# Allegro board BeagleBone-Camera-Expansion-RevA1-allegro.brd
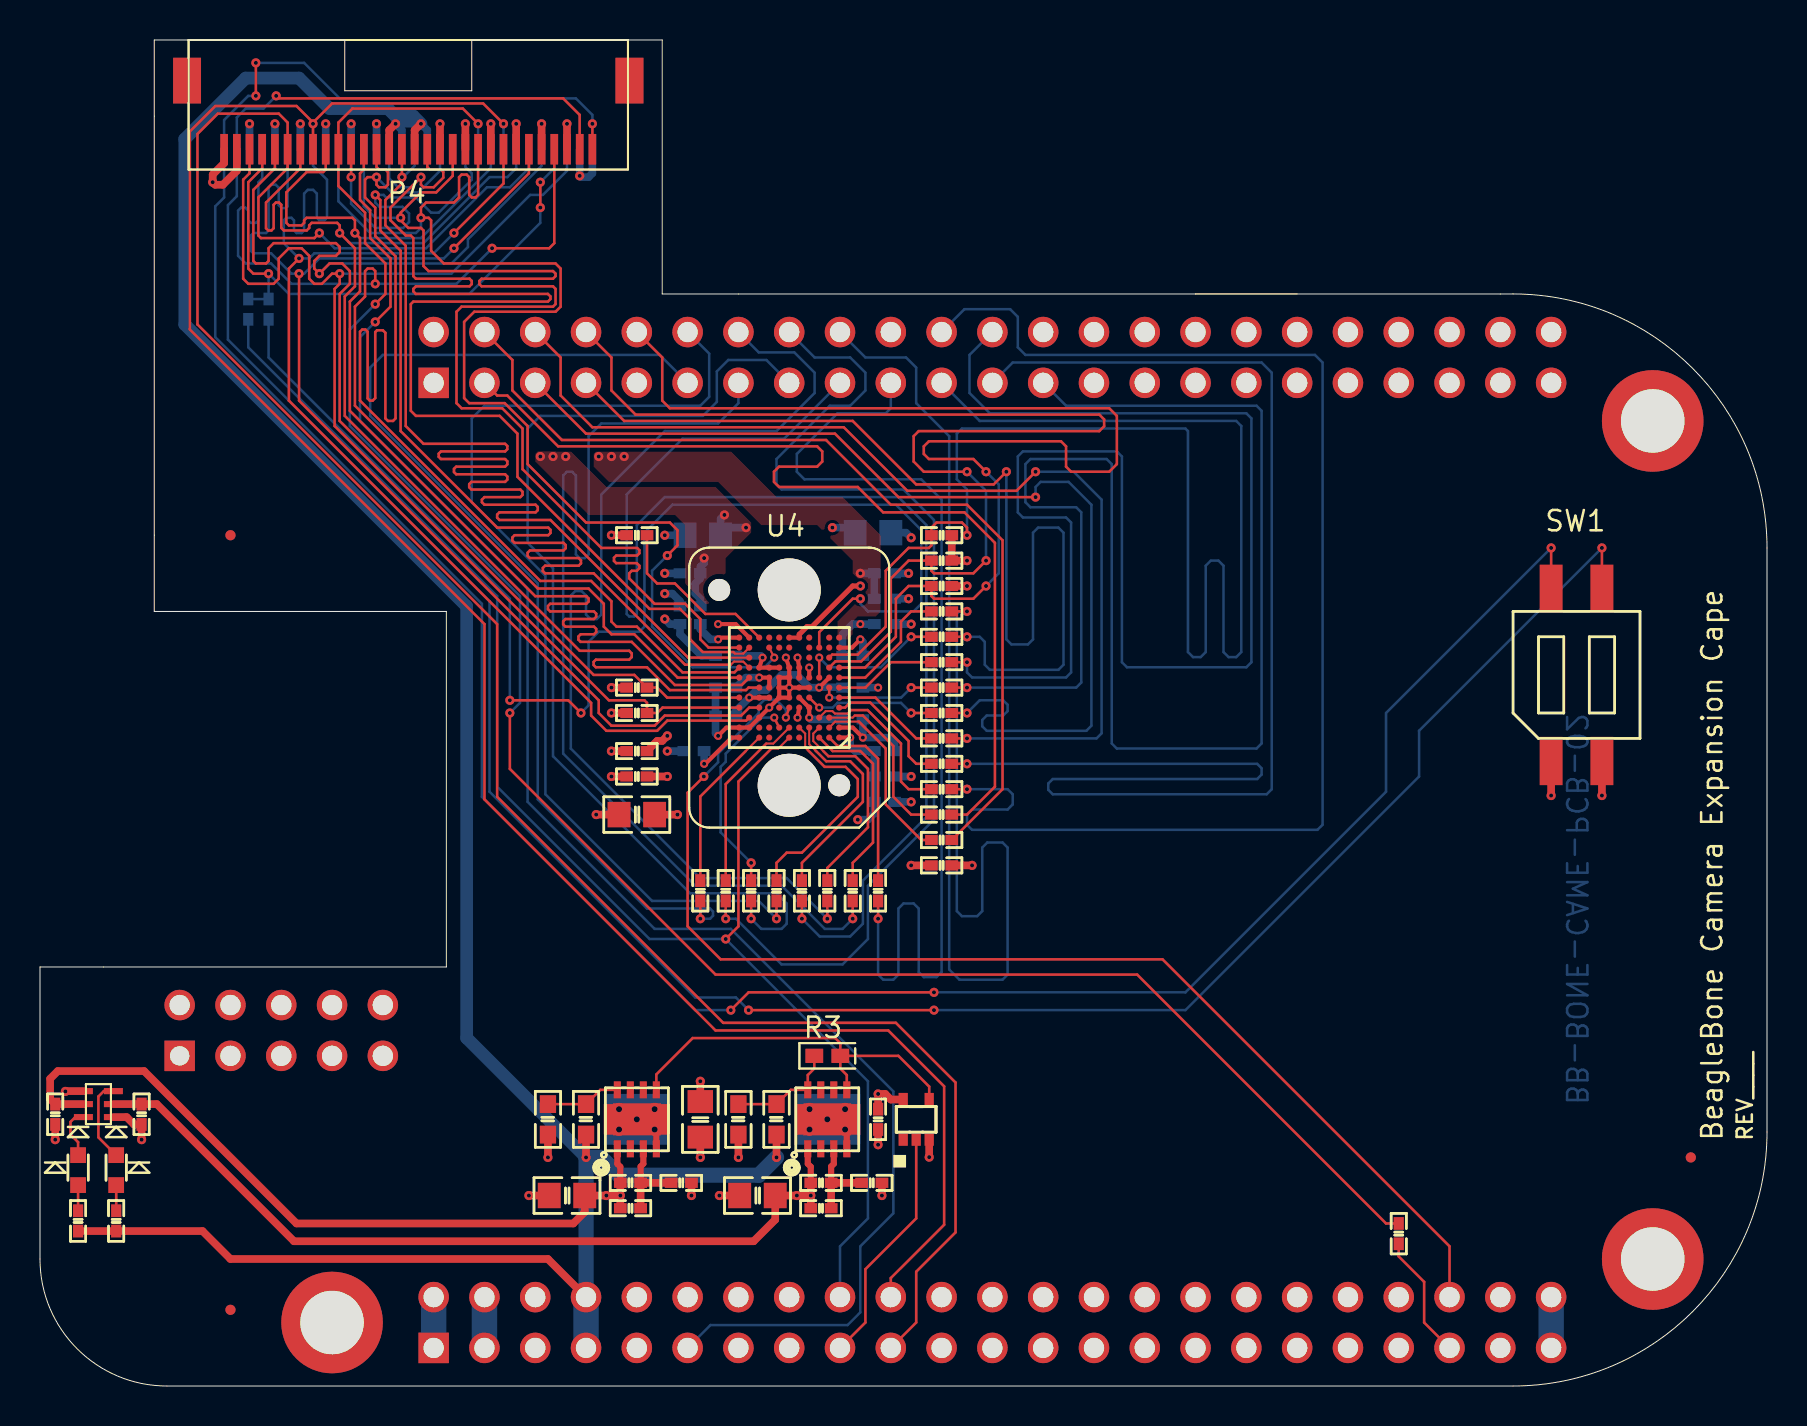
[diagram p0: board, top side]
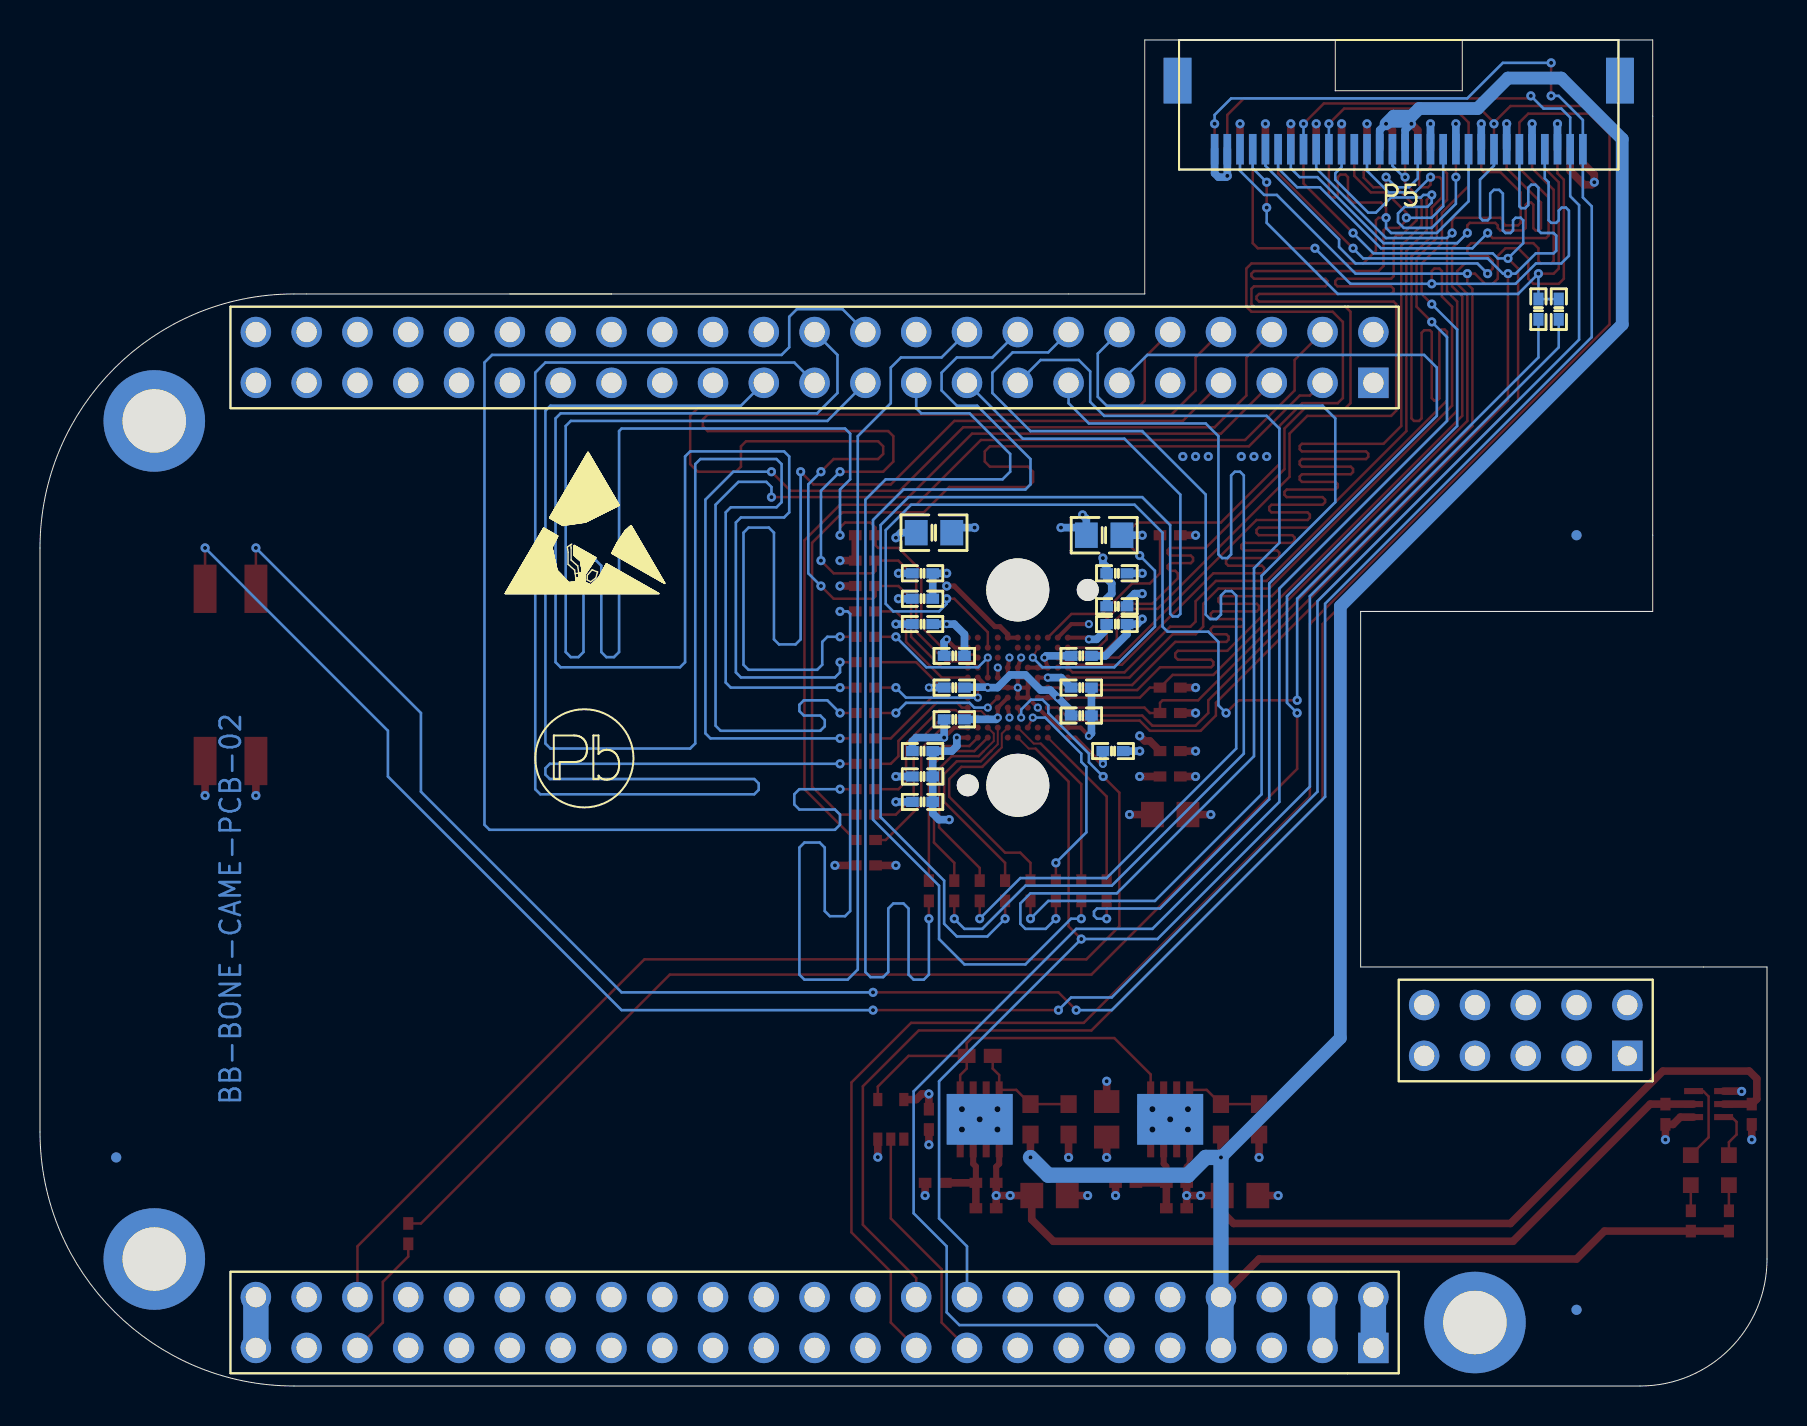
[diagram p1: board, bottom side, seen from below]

Outline 86.36 x 67.31 mm; copper layers: TOP, LYR2-GND, LYR3-PWR, BOTTOM. Coordinates in mm from the lower left corner of the outline.
Outline path: 57.78,54.61 31.11,54.61 31.11,67.31 21.59,67.31 21.59,64.77 15.24,64.77 15.24,67.31 5.71,67.31 5.71,38.73 20.32,38.73 20.32,20.95 0,20.95 0,6.35 arc(1.86,1.86) 6.35,0 73.66,0 arc(82.64,3.72) 86.36,12.7 86.36,41.91 arc(82.64,50.89) 73.66,54.61 57.78,54.61 ; 57.78,54.61 62.87,54.61

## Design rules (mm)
net group AD: nets AD0 AD1 AD2 AD3 AD4 AD5 AD6 AD7 AD8 AD9 AD10 AD11 AD12 AD13 AD14 AD15 GPMCCLK NADV
net group CAM: nets CAM_D0 CAM_D1 CAM_D2 CAM_D3 CAM_D4 CAM_D5 CAM_D6 CAM_D7 CAM_D8 CAM_D9 CAM_HSYNC CAM_PCLK CAM_VSYNC
net group GPMC: nets GPMC_AD0 GPMC_AD1 GPMC_AD2 GPMC_AD3 GPMC_AD4 GPMC_AD5 GPMC_AD6 GPMC_AD7 GPMC_AD8 GPMC_AD9 GPMC_AD10 GPMC_AD11 GPMC_AD12 GPMC_AD13 GPMC_AD14 GPMC_AD15 GPMC_CLK GPMC_NADV_ALE GPMC_NCS1 GPMC_NOE_NRE GPMC_NWE

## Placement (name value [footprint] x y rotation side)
C1  10uF,10V  [805]  33.02 13.34 270 top
C2  10uF,10V  [805]  29.84 28.57 0 top
C3  10uF,10V  [805]  35.88 9.53 0 top
C4  0.1uF  [402]  39.05 8.89 180 top
C5  0.1uF  [402]  29.53 8.89 180 top
C6  10uF,10V  [805]  26.35 9.53 0 top
C7  0.1uF  [402]  41.91 13.34 90 top
C8  0.1uF  [402]  40.64 33.34 180 bottom
C9  0.1uF  [402]  34.29 33.53 180 bottom
C10  0.1uF  [402]  32.7 31.75 180 bottom
C11  0.1uF  [402]  40.64 36.51 180 bottom
C12  0.1uF  [402]  34.29 36.51 180 bottom
C13  0.1uF  [402]  34.29 34.92 180 bottom
C14  0.1uF  [402]  45.09 26.04 180 top
C15  0.1uF  [402]  40.64 34.92 0 bottom
C16  0.1uF  [402]  32.51 38.1 180 bottom
C17  0.1uF  [402]  42.23 38.1 180 bottom
C18  0.1uF  [402]  29.84 31.75 180 top
C19  0.1uF  [402]  42.23 31.75 0 bottom
C20  0.1uF  [402]  32.51 38.99 180 bottom
C21  0.1uF  [402]  42.23 39.37 0 bottom
C22  0.1uF  [402]  32.51 40.64 180 bottom
C23  0.1uF  [402]  42.23 30.48 0 bottom
C24  0.1uF  [402]  42.23 40.64 0 bottom
C25  0.1uF  [402]  29.84 30.48 180 top
C26  0.1uF  [402]  42.23 29.21 0 bottom
C38  10uF,10V  [805]  41.66 42.67 0 bottom
C39  10uF,10V  [805]  33.15 42.55 0 bottom
D1  LTST-C190GKT  [LED2-31SQ]  3.81 10.79 270 top
D2  LTST-C190GKT  [LED2-31SQ]  1.91 10.79 270 top
NOREF  -  [unnamed]  80.64 48.26 0 top
NOREF#2  -  [#2]  86.36 12.7 0 top
NOREF#3  -  [unnamed]  82.55 11.43 0 top
NOREF#4  -  [#2]  0 0 0 top
NOREF#5  -  [#2]  0 0 0 top
NOREF#6  -  [#2]  1.84 1.88 0 top
NOREF#7  -  [#2]  80.64 6.35 0 top
NOREF#8  -  [unnamed]  80.64 6.35 0 top
NOREF#9  -  [#2]  14.61 3.17 0 top
NOREF#10  -  [#2]  81.6 2.79 0 top
NOREF#11  -  [unnamed]  9.53 3.81 0 top
NOREF#12  -  [unnamed#3]  37.47 34.92 180 top
NOREF#13  -  [#2]  80.64 6.35 0 top
NOREF#14  -  [unnamed]  14.61 3.17 0 top
NOREF#15  -  [#2]  -236.09 -292.66 0 top
NOREF#16  -  [#2]  14.61 3.17 0 top
NOREF#17  -  [unnamed]  9.53 42.55 0 top
NOREF#18  -  [#2]  0 20.95 0 top
NOREF#19  -  [#2]  20.32 20.95 0 top
NOREF#20  -  [#2]  80.64 48.26 0 top
NOREF#21  -  [#2]  5.71 38.73 0 top
NOREF#22  -  [#2]  -236.09 -292.66 0 top
NOREF#23  -  [unnamed]  82.55 11.43 180 bottom
NOREF#24  -  [unnamed]  9.53 42.55 180 bottom
NOREF#25  -  [unnamed]  9.53 3.81 180 bottom
P1  FEMALE HEADER 2x23  [HEADER23X2]  19.68 50.16 0 top
P2  FEMALE HEADER 2x23  [HEADER23X2]  19.68 1.91 0 top
P3  HDR5x2  [HEADER10X2]  6.99 16.51 90 top
P4  HEADER 15X2  [CON30SMD_245X865]  18.41 61.85 180 top
P5  HEADER 15X2  [CON30SMD_245X865]  18.41 61.85 0 bottom
Q1  DMC56404  [SMINI6-F3-B]  2.92 14.1 270 top
R1  0,DNI  [0603]  34.92 13.34 270 top
R2  0  [0603]  36.83 13.34 270 top
R3  10K  [0402]  39.37 16.51 180 top
R4  28K  [402]  39.05 10.16 180 top
R5  56.2K  [402]  41.59 10.16 0 top
R6  0,DNI  [0603]  25.4 13.34 270 top
R7  0  [0603]  27.3 13.34 270 top
R8  44.2k  [402]  29.53 10.16 180 top
R9  33.2k  [402]  32.07 10.16 0 top
R10  33  [402]  67.94 7.62 90 top
R11  10K,DNI  [402]  29.84 33.66 180 top
R12  33  [402]  45.09 31.11 180 top
R13  33  [402]  45.09 34.92 180 top
R16  33  [402]  45.09 36.2 180 top
R19  33  [402]  45.09 33.66 180 top
R22  10K,DNI  [402]  29.84 34.92 180 top
R23  33  [402]  45.09 32.38 180 top
R28  33  [402]  45.09 29.84 180 top
R29  33  [402]  45.09 28.57 180 top
R30  33  [402]  45.09 27.3 180 top
R31  33  [402]  41.91 24.77 90 top
R32  33  [402]  40.64 24.77 90 top
R33  33  [402]  39.37 24.77 90 top
R34  33  [402]  38.1 24.77 90 top
R35  33  [402]  36.83 24.77 90 top
R36  33  [402]  33.02 24.77 90 top
R37  33  [402]  34.29 24.77 90 top
R38  33  [402]  35.56 24.77 90 top
R39  33  [402]  45.09 38.73 180 top
R40  33  [402]  45.09 37.47 180 top
R41  10K,DNI  [402]  45.09 41.27 180 top
R42  10K,DNI  [402]  45.09 40.01 180 top
R43  10K,DNI  [402]  45.09 42.55 180 top
R44  0  [402]  10.41 53.85 270 bottom
R45  0, DNI  [402]  11.43 53.85 270 bottom
R55  470  [402]  3.81 8.26 270 top
R56  470  [402]  1.91 8.26 270 top
R59  10K  [402]  29.84 42.55 0 top
R121  100K,1%  [402]  5.08 13.59 270 top
R122  100K,1%  [402]  0.76 13.59 270 top
SW1  SW DIP-2  [SWDIP4_100-339SMD]  76.83 35.56 90 top
U1  TPS73701DRBR  [DRB8-14X33-PAD]  39.37 13.34 0 top
U2  TPS73701DRBR  [DRB8-14X33-PAD]  29.84 13.34 0 top
U3  SN74LVC1G07DCK  [DCK5]  43.81 13.34 0 top
U4  CSSP_6mmX6mm  [BGA86_6X6_P5MM]  37.47 34.92 180 top

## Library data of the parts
C1-C3 C6 C38 C39 = CAP_10uF_Y5V_10V_10%_0805
C4 C5 C7 = cap_0402_0r1uf_x7r_10v
C8-C26 = CAP,0.1uF
D1 D2 = LED_LTST-C150GKT: User Part Number: X; Tolerance: X
P1 P2 = HDR_46_F_2_0.1_0.1
P3 = HDR_10_F_2_0.1
P4 P5 = HEADER 15X2
Q1 = RN1907
R1-R3 R6 R7 R10 = ZeroOhmResistor1/16W0402
R4 R5 R8 R9 R11 R22 R41-R43 R59 = RES_0: tolerance: 1%
R12 R13 R16 R19 R23 R28-R40 R44 R45 = RES_33_0402
R55 R56 = RES_470_1/10W_5%_0402
R121 R122 = RES_100K_1/16W_1%_0402
SW1 = SW DIP-2
U1 U2 = TPS73701_0: Tolerance: X; User Part Number: X
U3 = SN74LVC1G06DCK_0: Tolerance: TOL; User Part Number: PART#
U4 = CSSP_0

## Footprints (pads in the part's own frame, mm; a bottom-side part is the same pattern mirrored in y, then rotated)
402
  rect 0.635x0.508 smd: 1(-0.508,0) 2(0.508,0)
0402
  rect 0.889x0.711 smd: 1(-0.65,0) 2(0.65,0)
0603
  rect 0.889x0.813 smd: 1(-0.762,0) 2(0.762,0)
805
  rect 1.143x1.27 smd: 1(-0.889,0) 2(0.889,0)
BGA86_6X6_P5MM
  round 0.305 smd: A1(-2.5,2.5) A2(-2,2.5) A3(-1.5,2.5) A5(-0.5,2.5) A6(0,2.5) A8(1,2.5) A9(1.5,2.5) A11(2.5,2.5) B1(-2.5,2) B2(-2,2) B3(-1.5,2) B4(-1,2) B5(-0.5,2) B6(0,2) B7(0.5,2) B8(1,2) B9(1.5,2) B10(2,2) B11(2.5,2) C2(-2,1.5) C3(-1.5,1.5) C9(1.5,1.5) C10(2,1.5) D1(-2.5,1) D4(-1,1) D5(-0.5,1) D6(0,1) D7(0.5,1) D9(1.5,1) D11(2.5,1) E1(-2.5,0.5) E4(-1,0.5) E5(-0.5,0.5) E6(0,0.5) E7(0.5,0.5) E8(1,0.5) E9(1.5,0.5) E11(2.5,0.5) F1(-2.5,0) F2(-2,0) F4(-1,0) F5(-0.5,0) F7(0.5,0) F8(1,0) F9(1.5,0) G1(-2.5,-0.5) G2(-2,-0.5) G3(-1.5,-0.5) G4(-1,-0.5) G5(-0.5,-0.5) G6(0,-0.5) G7(0.5,-0.5) G8(1,-0.5) G10(2,-0.5) G11(2.5,-0.5) H1(-2.5,-1) H2(-2,-1) H5(-0.5,-1) H6(0,-1) H7(0.5,-1) H8(1,-1) H9(1.5,-1) H10(2,-1) H11(2.5,-1) J2(-2,-1.5) J4(-1,-1.5) J10(2,-1.5) K1(-2.5,-2) K2(-2,-2) K3(-1.5,-2) K4(-1,-2) K6(0,-2) K7(0.5,-2) K8(1,-2) K10(2,-2) K11(2.5,-2) L1(-2.5,-2.5) L2(-2,-2.5) L4(-1,-2.5) L5(-0.5,-2.5) L6(0,-2.5) L7(0.5,-2.5) L8(1,-2.5) L9(1.5,-2.5) L10(2,-2.5) L11(2.5,-2.5)
CON30SMD_245X865
  rect 1.397x2.286 smd: (-11.062,-3.429) (11.062,-3.429)
  rect 0.381x1.524 smd: 1(8.572,0) 2(9.207,0) 3(7.303,0) 4(7.938,0) 5(6.032,0) 6(6.668,0) 7(4.763,0) 8(5.397,0) 9(3.493,0) 10(4.128,0) 11(2.223,0) 12(2.857,0) 13(0.953,0) 14(1.587,0) 15(-0.318,0) 16(0.318,0) 17(-1.587,0) 18(-0.953,0) 19(-2.857,0) 20(-2.223,0) 21(-4.128,0) 22(-3.493,0) 23(-5.397,0) 24(-4.763,0) 25(-6.668,0) 26(-6.032,0) 27(-7.938,0) 28(-7.303,0) 29(-9.207,0) 30(-8.572,0)
DCK5
  rect 0.46x0.66 smd: 1(-0.65,-0.991) 2(0,-0.991) 3(0.65,-0.991) 4(0.65,0.991) 5(-0.65,0.991)
DRB8-14X33-PAD
  rect 0.356x0.851 smd: 1(-0.975,-1.473) 2(-0.325,-1.473) 3(0.325,-1.473) 4(0.975,-1.473) 5(0.975,1.473) 6(0.325,1.473) 7(-0.325,1.473) 8(-0.975,1.473)
  rect 2.388x1.6 smd: 9(0,0)
HEADER10X2
  rect 1.524x1.524 hole 0.965: 1(0,0)
  round 1.524 hole 1.016: 2(2.54,0) 3(0,-2.54) 4(2.54,-2.54) 5(0,-5.08) 6(2.54,-5.08) 7(0,-7.62) 8(2.54,-7.62) 9(0,-10.16) 10(2.54,-10.16)
HEADER23X2
  rect 1.524x1.524 hole 1.016: 1(0,0)
  round 1.524 hole 1.016: 2(0,2.54) 3(2.54,0) 4(2.54,2.54) 5(5.08,0) 6(5.08,2.54) 7(7.62,0) 8(7.62,2.54) 9(10.16,0) 10(10.16,2.54) 11(12.7,0) 12(12.7,2.54) 13(15.24,0) 14(15.24,2.54) 15(17.78,0) 16(17.78,2.54) 17(20.32,0) 18(20.32,2.54) 19(22.86,0) 20(22.86,2.54) 21(25.4,0) 22(25.4,2.54) 23(27.94,0) 24(27.94,2.54) 25(30.48,0) 26(30.48,2.54) 27(33.02,0) 28(33.02,2.54) 29(35.56,0) 30(35.56,2.54) 31(38.1,0) 32(38.1,2.54) 33(40.64,0) 34(40.64,2.54) 35(43.18,0) 36(43.18,2.54) 37(45.72,0) 38(45.72,2.54) 39(48.26,0) 40(48.26,2.54) 41(50.8,0) 42(50.8,2.54) 43(53.34,0) 44(53.34,2.54) 45(55.88,0) 46(55.88,2.54)
LED2-31SQ
  rect 0.787x0.787 smd: 1(-0.749,0) 2(0.749,0)
SMINI6-F3-B
  rect 0.305x0.95 smd: 1(0.65,0.75) 2(0,0.75) 3(-0.65,0.75) 4(-0.65,-0.75) 5(0,-0.75) 6(0.65,-0.75)
SWDIP4_100-339SMD
  rect 2.413x1.143 smd: 1(-4.305,1.27) 2(-4.305,-1.27) 3(4.305,-1.27) 4(4.305,1.27)
unnamed
  round 5.08 hole 3.175: 1(0,0)
unnamed#3
  round 1.1 hole 1.1 unplated: (-2.5,4.885) (3.5,-4.885)
  round 3.15 hole 3.15 unplated: (0,4.885) (0,-4.885)

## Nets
1V8_FB: C4.1 R4.1(P1) R5.1(P1) U1.3(FB)
2V8_FB: C5.1 R8.1(P1) R9.1(P1) U2.3(FB)
DGND: C1.1 C2.1 C3.1 C6.1 C7.1 C8.1 C9.2 C10.2 C11.1 C12.2 C13.2 C14.1 C15.2 C16.2 C17.1 C18.2 C19.2 C20.2 C21.2 C22.2 C23.2 C24.2 C25.2 C26.2 C38.2 C39.1 P1.1 P1.2(26) P2.1 P2.2(26) P2.45(23) P2.46(48) P4.1 P4.2 P5.1 P5.2 Q1.1(4) Q1.4 R5.2(P2) R9.2(P2) R11.2(P2) R22.2(P2) R121.2 R122.2 SW1.1(A1) SW1.2(A2) U1.4(GND) U1.9(PAD) U2.4(GND) U2.9(PAD) U3.3(GND) U4.B1(GND1) U4.B10(CCMGND) U4.B11(GND2) U4.C9(CCMVCC1) U4.E6(GND11) U4.E7(GND12) U4.F4(GND3) U4.F5(GND4) U4.F7(GND5) U4.G6(GND6) U4.G7(GND7) U4.H6(GND8) U4.K1(GND9) U4.L5(GND13) U4.L6(GND14) U4.L10(GND10)
VDD_1V8: C2.2 C3.2 C4.2 C10.1 C13.1 C16.1 C19.1 C21.1 C23.1 C24.1 C25.1 C26.1 P4.25 P4.27 P5.25 P5.27 Q1.2(5) R4.2(P2) R121.1 U1.1(OUT) U4.A1(VCC1) U4.A11(VCC2) U4.D5(VCC3) U4.F8(VCC4) U4.G4(VCC5) U4.G8(VCC6) U4.L1(VCC7) U4.L11(VCC8)
VDD_2V8: C5.2 C6.2 C9.1 C12.1 C15.1 C18.1 C20.1 C22.1 C39.2 P4.21 P4.23 P5.21 P5.23 Q1.5 R8.2(P2) R122.1 U2.1(OUT) U4.E8(VCCIOA1) U4.E9(VCCIOA2) U4.G2(VCCIOB4) U4.H7(VCCIOB1) U4.H8(VCCIOB2) U4.H9(VCCIOB3)
VDD_3V3: C1.2 C7.2 C8.2 C11.2 C14.2 C17.2 C38.1 P2.3(2) P2.4(27) P4.17 P4.19 P5.17 P5.19 R1.2(P2) R6.2(P2) R41.1(P1) R42.1(P1) R43.1(P1) R59.1(P1) U3.5(VCC) U4.D4(VCCIOD1) U4.E5(VCCIOD2) U4.G5(VCCIOC1) U4.H5(VCCIOC2)
AD0: R13.2 U4.F2(GPMC_AD0)
AD1: R16.2 U4.F1(GPMC_AD1)
AD2: R19.2 U4.E4(GPMC_AD2)
AD3: R23.2 U4.E1(GPMC_AD3)
AD4: R12.2 U4.D1(GPMC_AD4)
AD5: R28.2 U4.C3(GPMC_AD5)
AD6: R29.2 U4.C2(GPMC_AD6)
AD7: R30.2 U4.B2(GPMC_AD7)
AD8: R31.2 U4.A2(GPMC_AD8)
AD9: R32.2 U4.A3(GPMC_AD9)
AD10: R33.2 U4.B3(GPMC_AD10)
AD11: R34.2 U4.B4(GPMC_AD11)
AD12: R35.2 U4.B5(GPMC_AD12)
AD13: R36.2 U4.A9(GPMC_AD13)
AD14: R37.2 U4.B6(GPMC_AD14)
AD15: R38.2 U4.B7(GPMC_AD15)
CAM_D0: P4.4 P5.4 R11.1(P1) U4.D11(CAM_D0)
CAM_D1: P4.6 P5.6 R22.1(P1) U4.E11(CAM_D1)
CAM_D2: P4.8 P5.8 U4.F9(CAM_D2)
CAM_D3: P4.10 P5.10 U4.G10(CAM_D3)
CAM_D4: P4.12 P5.12 U4.H10(CAM_D4)
CAM_D5: P4.14 P5.14 U4.H11(CAM_D5)
CAM_D6: P4.16 P5.16 U4.J10(CAM_D6)
CAM_D7: P4.18 P5.18 U4.K10(CAM_D7)
CAM_D8: P4.20 P5.20 U4.K11(CAM_D8)
CAM_D9: P4.22 P5.22 U4.K8(CAM_D9)
CAM_HSYNC: P4.26 P5.26 U4.D9(CAM_LINE_VALID)
CAM_MCLK: P4.9 P5.9 R10.2(P2)
CAM_PCLK: P4.28 P5.28 U4.G11(CAM_PCLK)
CAM_RESET: P4.3 P5.3 R44.1 R45.1
CAM_RST: R45.2 U4.K3(DNU8)
CAM_VSYNC: P4.24 P5.24 U4.C10(CAM_FRAME_VALID)
CLKOUT2: P2.41(21) R10.1(P1)
DMAR: P2.42(46) U4.D6(GPMC_DMAR)
GPIO0_4: P2.18(34) R44.2 U4.A6(NRESET)
GPIO0_5: P2.17(9) U3.2(A)
GPIO0_30: P2.11(6) P4.11
GPMC_AD0: P1.25(13) R13.1
GPMC_AD1: P1.24(37) R16.1
GPMC_AD2: P1.5(3) R19.1
GPMC_AD3: P1.6(28) R23.1
GPMC_AD4: P1.23(12) R12.1
GPMC_AD5: P1.22(36) R28.1
GPMC_AD6: P1.3(2) R29.1
GPMC_AD7: P1.4(27) R30.1
GPMC_AD8: P1.19(10) R31.1
GPMC_AD9: P1.13(7) R32.1
GPMC_AD10: P1.14(32) R33.1
GPMC_AD11: P1.17(9) R34.1
GPMC_AD12: P1.12(31) R35.1
GPMC_AD13: P1.11(6) R36.1
GPMC_AD14: P1.16(33) R37.1
GPMC_AD15: P1.15(8) R38.1
GPMC_CLK: P1.18(34) R39.1
GPMC_NADV_ALE: P1.7(4) R40.1
GPMC_NCS1: P1.21(11) R43.2(P2) U4.J2(GPMC_NCS)
GPMC_NOE_NRE: P1.8(29) R41.2(P2) U4.H2(GPMC_NOE)
GPMC_NWE: P1.10(30) R42.2(P2) U4.H1(GPMC_NWE)
GPMCCLK: R39.2 U4.G1(GPMC_CLK)
I2C2_SCL: P2.19(10) P4.5 P5.5
I2C2_SDA: P2.20(35) P4.7 P5.7
LDO_EN: R3.1(P1) U1.5(EN) U2.5(EN) U3.4(Y)
NADV: R40.2 U4.G3(GPMC_NADV)
SW1_A0: P4.29 P5.29 SW1.4(B1)
SW1_A1: P4.30 P5.30 SW1.3(B2)
SYS_5V: P2.7(4) P2.8(29) P4.13 P4.15 P5.13 P5.15 R2.2(P2) R7.2(P2) R55.2 R56.2
N17041351: R1.1(P1) R2.1(P1) R3.2(P2) U1.8(IN)
N17041584: R6.1(P1) R7.1(P1) U2.8(IN)
N17068057: R59.2(P2) U4.L9(VLP)
N17096906: D2.1(C) Q1.6(3)
N17096909: D2.2(A) R56.1
N17096919: D1.1(C) Q1.3
N17096922: D1.2(A) R55.1

Pads without a net: NOREF 1; NOREF#3 1; NOREF#8 1; NOREF#11 1; NOREF#14 1; NOREF#17 1; NOREF#23 1; NOREF#24 1; NOREF#25 1; P1 9 20 26 27 28 29 30 31 32 33 34 35 36 37 38 39 40 41 42 43 44 45 46; P2 5 6 9 10 12 13 14 15 16 21 22 23 24 25 26 27 28 29 30 31 32 33 34 35 36 37 38 39 40 43 44; P3 1 2 3 4 5 6 7 8 9 10; P5 11; U1 2 6 7; U2 2 6 7; U3 1; U4 A5 A8 B8 B9 D7 J4 K2 K4 K6 K7 L2 L4 L7 L8

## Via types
v1: diameter 0.457, hole 0.203, TOP to BOTTOM, 146 vias
v2: diameter 0.406, hole 0.203, TOP to BOTTOM, 26 vias
v3: diameter 0.635, hole 0.305, TOP to BOTTOM, 10 vias

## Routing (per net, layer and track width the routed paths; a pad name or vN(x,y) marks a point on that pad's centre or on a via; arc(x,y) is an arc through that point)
1V8_FB: length 4.6
  TOP w0.305: R4.1 39.56,10.98 39.7,11.11 U1.3
  TOP w0.381: R5.1 R4.1 C4.1
2V8_FB: length 4.6
  TOP w0.305: R8.1 30.04,10.98 30.17,11.11 U2.3
  TOP w0.381: R9.1 R8.1 C5.1
DGND: length 100.5
  TOP w0.203: U4.B1 40.65,32.93 v2(41.15,32.42) ; v2(37.47,34.92) U4.F5 U4.F4 ; v2(37.47,34.92) U4.F7 ; v2(37.47,34.92) U4.E6 U4.E7 ; v2(37.47,34.92) U4.G6 ; U4.F7 U4.E7 ; U4.F7 U4.G7 U4.G6 ; U4.G6 U4.H6 v2(37.3,36.43) ; U4.E7 v2(36.47,33.93) U4.C9 U4.B10 U4.B11 34.32,32.93 v2(33.91,32.51) ; v2(33.91,38.1) 34.79,38.1 U4.L10 ; v2(41.02,37.34) 40.61,36.92 U4.K1 ; U4.L6 U4.L5
  TOP w0.254: v1(41.02,40.01) 40.64,40.01 38.61,37.97 38.35,37.97 37.97,37.58 U4.L5
  TOP w0.305: U2.4 30.82,12.74 v3(30.73,12.83) ; v3(40.26,12.83) 40.35,12.74 U1.4
  TOP w0.381: v1(1.27,14.73) 1.28,14.75 Q1.4 ; C2.1 v1(27.81,28.57) ; R5.2 v1(42.1,9.53) ; C7.1 v1(41.91,12.06) ; R122.2 v1(0.76,12.32) ; C6.1 v1(24.45,9.53) ; C18.2 v1(28.57,31.75) ; C25.2 v1(28.57,30.48) ; R11.2 v1(28.57,33.66) ; C1.1 v1(33.02,15.24) ; P4.1 9.84,60.77 9.14,60.07 8.76,60.07 v1(8.64,60.2) 8.64,60.58 9.21,61.15 P4.2 ; R9.2 v1(32.58,9.53) ; C14.1 v1(46.61,26.04) ; SW1.2 v1(78.11,29.53) ; U3.3 v1(44.47,11.45) ; v1(28.57,34.92) R22.2 ; v1(5.08,12.32) R121.2 4.7,13.08 4.33,13.45 Q1.1 ; SW1.1 v1(75.56,29.53) ; C3.1 v1(33.97,9.53)
  LYR2-GND w1.016: P2.46 76.33,5.21 ; P2.46 74.8,3.68 ; P2.46 74.8,5.21 ; P2.46 76.33,3.68 ; 18.67,0.89 P2.1 ; P2.1 20.7,0.89 ; P2.1 20.7,2.92 ; P2.1 18.67,2.92 ; P2.2 20.45,3.68 ; P2.2 18.92,3.68 ; P2.2 18.92,5.21 ; P2.2 20.45,5.21 ; 18.67,49.15 P1.1 ; P1.1 20.7,51.18 ; P1.1 20.7,49.15 ; P1.1 18.67,51.18 ; 18.92,51.94 P1.2 ; P1.2 20.45,51.94 ; P1.2 20.45,53.47 ; P1.2 18.92,53.47 ; P2.45 76.33,1.14 ; P2.45 74.8,2.67 ; P2.45 74.8,1.14 ; P2.45 76.33,2.67
  BOTTOM w0.381: C17.1 v1(43.56,38.1) ; C10.2 v1(31.37,31.75) ; C39.1 v1(31.24,42.55) ; C11.1 41.15,37.21 v2(41.02,37.34) ; C26.2 v1(43.56,29.21) ; P5.2 27.62,60.64 27.43,60.45 27.05,60.45 v1(26.99,60.52) P5.1 ; C38.2 43.31,42.67 v1(43.56,42.42) ; C23.2 v1(43.56,30.48) ; C22.2 v1(31.24,40.64) ; C21.2 v1(43.43,39.37) ; C24.2 v1(43.43,40.64) ; v1(31.24,39.62) 31.62,39.62 32,39.24 C20.2 ; v1(31.24,38.35) 31.5,38.1 C16.2 32,37.59 33.08,36.51 C12.2 ; C15.2 v2(41.91,34.92) ; v2(33.91,32.51) 33.78,32.64 C9.2 C13.2 ; C8.1 v2(41.15,32.42) 42.55,32.42 42.74,32.23 C19.2
  BOTTOM w1.27: P2.1 P2.2 ; P2.45 P2.46
  vias: v3(28.96,13.84) v3(28.96,12.83) v3(29.84,13.34) v3(30.73,13.84) v3(38.48,13.84) v3(38.48,12.83) v3(39.37,13.34) v3(40.26,13.84)
VDD_1V8: length 66.8
  TOP w0.203: U4.L11 34,37.43 v2(33.91,37.34) ; v2(33.21,31.11) 33.21,31.05 34.58,32.42 U4.A11 ; U4.D5 v2(37.88,33.42) ; U4.F8 U4.G8 v2(35.96,35.43) ; U4.G4 v2(38.46,35.92) ; v2(40.51,32.42) U4.A1
  TOP w0.305: R4.2 38.54,10.96 38.39,11.11 U1.1
  TOP w0.381: v1(38.54,9.53) C4.2 ; v1(38.54,9.53) v1(37.85,9.53) C3.2 36.77,8.32 35.69,7.24 12.7,7.24 5.84,14.1 Q1.2 ; v1(38.54,9.53) R4.2 ; P4.27 v1(26.35,63.12) ; C2.2 v1(31.88,28.57) ; C25.1 v1(31.37,30.48) ; P4.25 v1(25.08,63.12)
  BOTTOM w0.381: v2(35.96,35.43) 35.3,35.43 C13.1 ; C16.1 33.02,37.85 33.53,37.34 v2(33.91,37.34) ; v2(40.51,32.42) 40.51,32 40.77,31.75 C19.1 C23.1 C26.1 41.72,28.64 41.4,28.32 v1(40.89,28.32) ; C21.1 C24.1 v1(41.02,40.64) ; C10.1 v2(33.21,31.11) ; P5.25 v1(11.75,63.12) ; P5.27 v1(10.48,63.12)
  vias: v1(27.94,46.48) v1(28.57,46.48) v1(29.21,46.48)
VDD_2V8: length 61.5
  TOP w0.203: U4.G2 v2(38.97,34.92) ; v2(35.47,34.42) U4.E9 U4.E8 ; U4.H7 U4.H8 U4.H9 v2(36.13,36.43)
  TOP w0.305: R8.2 29.02,10.96 28.87,11.11 U2.1
  TOP w0.381: v1(31.37,32.51) 31.11,32.26 30.86,32.26 C18.1 ; v1(29.02,9.53) v1(28.32,9.53) C6.2 27.24,8.7 26.67,8.13 12.83,8.13 5.21,15.75 0.89,15.75 0.51,15.37 0.51,14.35 0.76,14.1 Q1.5 ; v1(29.02,9.53) R8.2 ; v1(29.02,9.53) C5.2 ; P4.23 v1(23.81,63.12) ; P4.21 v1(22.54,63.12)
  BOTTOM w0.381: v1(33.21,41.4) 33.21,41.15 33.02,40.96 C22.1 33.02,40.39 32.77,40.13 32.77,39.62 33.02,39.37 C20.1 ; P5.23 v1(13.02,63.12) ; v1(34.23,43.56) 34.04,43.37 C39.2 34.42,42.93 v1(35.31,42.93) ; C12.1 36.04,36.51 v2(36.13,36.43) ; C9.1 34.8,33.76 v2(35.47,34.42) 35.84,34.8 36.32,34.8 37.08,35.56 37.85,35.56 38.48,34.92 v2(38.97,34.92) 38.99,34.95 40.11,34.95 C15.1 ; P5.21 v1(14.29,63.12)
  vias: v1(25.02,46.48) v1(25.65,46.48) v1(26.29,46.48)
VDD_3V3: length 34.4
  TOP w0.203: v2(37.88,36.43) U4.H5 U4.G5 ; v2(38.46,33.42) U4.D4 U4.E5
  TOP w0.381: U3.5 42.55,14.33 42.27,14.61 v1(41.91,14.61) C7.2 ; R1.2 v1(34.92,11.43) ; R42.1 v1(46.35,40.01) ; v1(46.35,41.27) R41.1 R43.1 ; P4.19 v1(21.27,63.12) ; C1.2 v1(33.02,11.43) ; C14.2 v1(43.56,26.04) ; R6.2 v1(25.4,11.43) ; v1(28.57,42.55) R59.1 ; P4.17 v1(20,63.12)
  LYR3-PWR w0.381: 38.46,33.42 v2(38.46,33.42)
  LYR3-PWR w1.016: P2.3 22.99,1.14 ; P2.3 22.99,2.67 ; P2.3 21.46,1.14 ; P2.3 21.46,2.67 ; P2.4 22.99,5.21 ; P2.4 21.46,3.68 ; P2.4 21.46,5.21 ; P2.4 22.99,3.68
  BOTTOM w0.381: v1(39.62,42.93) 40.51,42.93 40.77,42.67 ; P5.17 v1(16.83,63.12) ; C8.2 38.55,33.34 v2(38.46,33.42) ; C11.2 40.13,37.59 40.64,38.1 v2(41.02,38.1) C17.2 ; P5.19 v1(15.56,63.12)
  BOTTOM w1.27: P2.3 P2.4
AD0: length 5.8
  TOP w0.127: U4.F2 v2(39.46,34.42) ; R13.2 v1(43.56,34.92)
  BOTTOM w0.127: v2(39.46,34.42) 43.06,34.42 v1(43.56,34.92)
AD1: length 5.1
  TOP w0.127: R16.2 42.55,36.2 41.27,34.92 U4.F1
AD2: length 6.6
  TOP w0.127: R19.2 v1(43.56,33.66) ; U4.E4 v2(38.97,33.93)
  BOTTOM w0.127: v1(43.56,33.66) 43.05,34.16 39.88,34.16 39.64,33.93 v2(38.97,33.93)
AD3: length 5.5
  TOP w0.127: U4.E1 41.78,34.42 43.81,32.38 R23.2
AD4: length 6.4
  TOP w0.127: U4.D1 40.26,33.93 40.51,34.17 41.52,34.17 43.43,32.26 43.43,31.5 43.81,31.11 R12.2
AD5: length 8.6
  TOP w0.102: U4.C3 39.29,33.75 39.63,33.75 39.75,33.63 40.39,33.63 40.56,33.8
  TOP w0.127: R28.2 43.43,29.84 43.05,30.23 43.05,32.13 41.38,33.8 40.56,33.8
AD6: length 8.7
  TOP w0.102: U4.C2 40.64,33.42 40.74,33.53
  TOP w0.127: 40.74,33.53 41.15,33.53 42.67,32 42.67,29.46 43.56,28.57 R29.2
AD7: length 9.3
  TOP w0.102: 40.94,33.22 39.76,33.22 U4.B2
  TOP w0.127: R30.2 44.07,27.3 42.29,29.08 42.29,31.88 40.94,33.22
AD8: length 9
  TOP w0.127: R31.2 41.91,31.37 41.27,32 39.89,32 U4.A2
AD9: length 9.5
  TOP w0.127: R32.2 40.64,26.16 41.66,27.18 41.66,31.11 41.02,31.75 39.64,31.75 U4.A3
AD10: length 10.5
  TOP w0.102: 39.17,31.75 38.67,32.25 38.67,32.63 U4.B3
  TOP w0.127: R33.2 39.37,25.91 41.4,27.94 41.4,30.86 40.77,31.5 39.42,31.5 39.17,31.75
AD11: length 10.7
  TOP w0.102: U4.B4 38.46,32.09 38.77,31.79
  TOP w0.127: 38.77,31.79 39.32,31.24 40.51,31.24 41.15,30.61 41.15,29.21 38.1,26.16 R34.2
AD12: length 11.6
  TOP w0.102: U4.B5 38.26,32.63 38.26,31.94 38.4,31.8
  TOP w0.127: 38.4,31.8 39.24,30.96 40.29,30.96 40.89,30.35 40.89,29.46 38.1,26.67 37.34,26.67 36.83,26.16 R35.2
AD13: length 8.4
  TOP w0.102: 35.29,31.75 U4.A9
  TOP w0.127: R36.2 33.02,29.48 35.29,31.75
AD14: length 9.2
  TOP w0.102: 36.32,32.13 36.67,32.13 U4.B6
  TOP w0.127: R37.2 34.29,30.1 36.32,32.13
AD15: length 10.8
  TOP w0.127: R38.2 v1(35.56,26.16) ; U4.B7 v2(36.71,33.42)
  BOTTOM w0.127: v2(36.71,33.42) 36.09,33.42 34.29,31.62 34.29,31.21 34.04,30.96 34.04,27.69 v1(35.56,26.16)
CAM_D0: length 63.4
  TOP w0.127: P4.4 10.48,60.64 10.16,60.33 10.16,55.37 10.41,55.12 11.68,55.12 11.94,55.37 11.94,56.39 12.45,56.9 13.08,56.9 13.46,56.52 13.46,55.37 13.72,55.12 14.1,55.12 14.61,55.63 v1(14.99,55.63) 14.99,55.12 14.73,54.86 14.73,48.01 28.45,34.29 30.23,34.29 30.35,34.16 R11.1 30.86,33.66 31.13,33.93 U4.D11
  BOTTOM w0.127: P5.4 26.35,60.77 25.15,59.56 24.51,59.56 20.57,55.63 v1(14.99,55.63)
CAM_D1: length 63.4
  TOP w0.127: U4.E11 31.36,34.42 30.86,34.92 R22.1 29.72,35.56 27.69,35.56 14.99,48.26 14.99,54.61 15.49,55.12 15.49,55.75 15.11,56.13 14.48,56.13 v1(13.97,55.63) 13.72,55.88 13.72,56.26 13.97,56.52 14.8,56.52 14.99,56.7 14.99,56.96 14.8,57.15 11.68,57.15 11.43,56.9 11.43,56.26 11.3,56.13 10.79,56.13 10.67,56.26 10.67,59.82 11.75,60.9 P4.6
  BOTTOM w0.127: P5.6 25.08,61.02 21.4,57.34 21.4,56.96 20.57,56.13 14.48,56.13 v1(13.97,55.63)
CAM_D2: length 63.3
  TOP w0.127: U4.F9 35.43,34.92 35.31,34.8 31.49,34.8 30.35,35.94 27.8,35.94 27.69,36.05 27.69,36.21 27.8,36.32 29.46,36.32 29.59,36.45 29.59,36.64 29.46,36.77 26.99,36.77 15.24,48.51 15.24,54.48 15.75,54.99 15.75,56.9 v1(14.99,57.66) 14.99,58.04 14.86,58.17 13.59,58.17 13.46,58.04 13.46,57.91 13.34,57.78 12.19,57.78 12.06,57.91 12.06,59.07 11.95,59.18 11.8,59.18 11.68,59.07 11.68,57.9 11.57,57.78 11.41,57.78 11.3,57.9 11.3,59.18 13.02,60.9 P4.8
  BOTTOM w0.127: P5.8 23.81,60.9 23.37,60.45 22.48,60.45 19.18,57.15 15.49,57.15 v1(14.99,57.66)
CAM_D3: length 63.4
  TOP w0.127: U4.G10 35.09,35.05 31.75,35.05 29.59,37.21 27.04,37.21 26.92,37.32 26.92,37.48 27.04,37.59 27.7,37.59 27.81,37.7 27.81,37.86 27.7,37.97 26.27,37.97 26.16,38.08 26.16,38.24 26.27,38.35 27.7,38.35 27.81,38.47 27.81,38.62 27.7,38.73 25.51,38.73 25.4,38.85 25.4,39 25.51,39.12 27.32,39.12 27.43,39.23 27.43,39.39 27.32,39.5 24.77,39.5 15.49,48.77 15.49,54.23 16,54.74 16,57.4 v1(15.75,57.66) 15.75,58.29 15.62,58.42 13.34,58.42 13.21,58.29 13.21,58.17 13.08,58.04 12.45,58.04 12.32,58.17 12.32,59.69 13.34,60.71 14.16,60.71 14.29,60.83 P4.10
  BOTTOM w0.127: v1(15.75,57.66) 16,57.4 19.05,57.4 22.54,60.9 P5.10
CAM_D4: length 63.3
  TOP w0.102: 34.54,36.07 34.7,36.22 35.17,36.22 U4.H10
  TOP w0.127: v1(16.76,59.56) 17.02,59.31 17.02,57.78 18.03,56.77 18.03,47.75 22.86,42.93 25.42,42.93 25.53,42.81 25.53,42.66 25.42,42.55 23.73,42.55 23.62,42.43 23.62,42.28 23.73,42.16 26.18,42.16 26.29,42.05 26.29,41.89 26.18,41.78 24.5,41.78 24.38,41.67 24.38,41.51 24.5,41.4 26.94,41.4 27.05,41.29 27.05,41.13 26.94,41.02 25.26,41.02 25.15,40.91 25.15,40.75 25.26,40.64 27.69,40.64 32.26,36.07 34.54,36.07 ; P4.12 v1(15.56,60.45)
  BOTTOM w0.127: P5.12 21.27,60.96 21.59,60.64 21.59,60.33 19.94,58.67 19.56,58.67 18.8,59.44 17.31,59.44 17.18,59.56 v1(16.76,59.56) 16.76,59.18 16.98,58.97 18.12,58.97 18.45,58.64 18.45,58.2 18.16,57.91 16.76,57.91 15.56,59.12 v1(15.56,60.45)
CAM_D5: length 63.3
  TOP w0.127: U4.H11 34.73,35.69 32.13,35.69 29.84,37.97 28.83,37.97 28.57,38.23 28.57,39.24 27.56,40.26 25.02,40.26 16,49.28 16,52.72 16.11,52.83 16.27,52.83 16.38,52.72 16.38,49.39 16.49,49.28 16.64,49.28 16.76,49.4 16.76,52.7 16.85,52.79 17.14,52.79 17.27,52.67 17.27,48.39 17.4,48.26 17.65,48.26 17.78,48.39 17.78,56.49 16.76,57.51 16.76,58.93 16.26,59.44 16.26,60.33 16.38,60.45 v1(16.83,60.45) 16.83,60.07 16.95,59.94 17.27,59.94 17.4,60.07 17.4,60.71 17.27,60.83 16.95,60.83 16.83,60.96 P4.14
  BOTTOM w0.127: P5.14 20,60.77 18.92,59.69 17.59,59.69 v1(16.83,60.45)
CAM_D6: length 63.3
  TOP w0.102: U4.J10 34.44,36.43
  TOP w0.127: P4.16 v1(18.1,60.45) 18.1,60.13 17.27,59.31 17.27,58.04 18.29,57.02 18.29,48.01 19.18,47.12 23.26,47.12 23.37,47.01 23.37,46.85 23.26,46.74 20.05,46.74 19.94,46.62 19.94,46.47 20.05,46.35 23.26,46.35 23.37,46.24 23.37,46.09 23.26,45.97 20.81,45.97 20.7,45.86 20.7,45.7 20.81,45.59 23.26,45.59 23.37,45.48 23.37,45.32 23.26,45.21 21.57,45.21 21.46,45.1 21.46,44.94 21.57,44.83 24.02,44.83 24.13,44.72 24.13,44.56 24.02,44.45 22.23,44.45 22.1,44.32 22.1,44.2 22.23,44.07 24.78,44.07 24.89,43.96 24.89,43.8 24.78,43.69 22.97,43.69 22.86,43.58 22.86,43.42 22.97,43.31 25.53,43.31 32.41,36.43 34.44,36.43
  BOTTOM w0.127: P5.16 18.73,61.02 18.16,60.45 v1(18.1,60.45)
CAM_D7: length 63.2
  TOP w0.102: 34.67,36.7 34.75,36.63 35.17,36.63 U4.K10
  TOP w0.127: P4.18 19.37,60.96 19.49,60.83 20.04,60.83 20.17,60.71 20.17,60.43 19.68,59.94 19.18,59.94 19.05,60.07 v1(19.05,60.45) 17.53,58.93 17.53,58.29 18.29,57.53 18.54,57.53 18.67,57.4 18.67,55.5 18.8,55.37 21.48,55.37 21.59,55.26 21.59,55.1 21.48,54.99 18.8,54.99 18.67,54.86 18.67,54.74 18.8,54.61 25.4,54.61 25.53,54.48 25.53,54.36 25.4,54.23 18.67,54.23 18.54,54.1 18.54,48.77 18.8,48.51 22.99,48.51 23.88,47.62 23.88,45.47 30.48,38.86 32,38.86 32.51,38.35 32.51,37.34 33.15,36.7 34.67,36.7
  BOTTOM w0.127: P5.18 17.46,60.39 17.91,59.94 18.54,59.94 v1(19.05,60.45)
CAM_D8: length 63.4
  TOP w0.127: U4.K11 34.96,36.93 33.43,36.93 33.02,37.34 33.02,38.35 32.26,39.12 30.73,39.12 29.46,40.39 29.46,40.64 29.59,40.77 29.84,40.77 29.97,40.89 29.97,41.02 29.84,41.15 28.81,41.15 28.7,41.26 28.7,41.42 28.81,41.53 29.86,41.53 29.97,41.64 29.97,41.8 29.86,41.91 28.07,41.91 24.13,45.85 24.13,47.88 23.11,48.9 21.08,48.9 20.83,49.15 20.83,53.72 21.08,53.98 25.65,53.98 25.78,54.1 25.78,54.86 25.65,54.99 22.08,54.99 21.97,55.1 21.97,55.26 22.08,55.37 25.65,55.37 25.78,55.5 25.78,55.63 25.65,55.75 19.43,55.75 19.18,56.01 19.18,57.78 19.05,57.91 18.41,57.91 18.03,58.29 v1(18.03,58.42) 18.03,58.67 19.05,59.69 19.81,59.69 20.64,60.52 P4.20
  BOTTOM w0.127: P5.20 16.19,58.99 16.76,58.42 v1(18.03,58.42)
CAM_D9: length 63.3
  TOP w0.102: v2(36.71,36.43) U4.K8
  TOP w0.127: P4.22 21.91,59.56 21.78,59.44 21.59,59.44 21.46,59.56 21.46,60.45 21.34,60.58 21.08,60.58 20.95,60.45 20.95,59.44 20.7,59.18 19.3,59.18 19.05,58.93 v1(19.05,58.42) 19.43,58.42 19.56,58.29 19.56,56.77 20.19,56.13 25.78,56.13 26.04,55.88 26.04,53.98 25.78,53.72 21.72,53.72 21.21,53.21 21.21,49.4 21.46,49.15 23.24,49.15 24.38,48.01 24.38,46.1 27.3,43.18 31.5,43.18 31.88,42.8 31.88,42.04 v1(31.37,41.53)
  BOTTOM w0.127: P5.22 14.92,59.25 16.51,57.66 18.8,57.66 19.05,57.91 v1(19.05,58.42) ; v2(36.71,36.43) 36.23,35.94 32.64,35.94 30.61,37.97 30.61,40.77 v1(31.37,41.53)
CAM_HSYNC: length 63.3
  TOP w0.127: v1(12.95,55.63) 12.95,49.28 27.94,34.29 27.94,33.66 28.57,33.02 30.73,33.02 31.24,33.53 35.07,33.53 35.47,33.93 U4.D9 ; v1(20.7,56.9) 24.45,60.64 P4.26
  BOTTOM w0.127: P5.26 12.38,58.99 12.29,58.9 12.09,58.9 11.94,59.05 11.94,59.92 11.79,60.07 11.58,60.07 11.43,59.92 11.43,57.78 11.3,57.66 10.67,57.66 10.54,57.53 10.54,56.77 10.67,56.64 11.56,56.64 12.57,55.63 v1(12.95,55.63) 13.21,55.63 13.97,56.39 20.19,56.39 v1(20.7,56.9)
CAM_MCLK: length 100.5
  TOP w0.127: v1(16.76,54.1) 17.27,54.61 17.27,56.13 16.26,57.15 16.26,58.67 14.92,60.01 P4.9 14.92,63.18 15.62,63.88 21.15,63.88 v1(21.91,63.12) ; v1(23.5,33.66) 23.5,30.86 33.78,20.57 54.86,20.57 67.31,8.13 R10.2
  BOTTOM w0.127: v1(23.5,33.66) 24,34.16 24,39.5 15.49,48.01 15.49,52.83 v1(16.76,54.1) ; P5.9 v1(21.91,63.12)
CAM_PCLK: length 63.3
  TOP w0.127: U4.G11 31.88,35.43 29.72,37.59 28.57,37.59 28.19,37.97 28.19,39.12 27.43,39.88 24.89,39.88 15.75,49.02 15.75,53.98 16.26,54.48 16.26,55.75 16.38,55.88 16.64,55.88 16.76,55.75 v1(16.76,55.12) ; P4.28 25.72,57.15 25.46,56.9 v1(22.61,56.9)
  BOTTOM w0.127: P5.28 11.11,60.39 10.92,60.2 10.92,58.29 10.79,58.17 10.54,58.17 10.41,58.29 10.41,58.78 10.27,58.93 10.05,58.93 9.91,58.78 9.91,56.52 10.29,56.13 11.56,56.13 12.57,55.12 v1(16.76,55.12) 20.83,55.12 v1(22.61,56.9)
CAM_RESET: length 29.1
  TOP w0.127: v1(11.43,55.63) 10.67,55.63 10.41,55.88 10.41,60.2 11.11,60.9 P4.3 ; v1(25.02,60.2) v1(25.02,58.93)
  BOTTOM w0.127: v1(25.02,60.2) 25.72,60.9 P5.3 ; v1(25.02,58.93) 25.02,58.17 21.46,54.61 12.45,54.61 v1(11.43,55.63) R45.1 R44.1
CAM_RST: length 65.2
  TOP w0.127: v1(41.02,39.37) 40.64,39.37 38.97,37.7 U4.K3 ; v1(23.5,34.29) 26.42,34.29 v1(27.05,33.66)
  BOTTOM w0.127: v1(41.02,39.37) 41.02,39.12 41.4,38.73 43.69,38.73 44.07,39.12 44.07,42.8 42.8,44.07 31.62,44.07 30.23,42.67 30.23,37.97 29.97,37.72 27.94,37.72 27.43,37.21 27.43,34.04 v1(27.05,33.66) ; R45.2 11.43,51.44 23.5,39.37 v1(23.5,34.29)
CAM_VSYNC: length 63.4
  TOP w0.127: U4.C10 35.31,33.27 31.37,33.27 30.86,32.77 28.32,32.77 27.56,33.53 27.56,34.16 12.45,49.28 12.45,55.88 v1(12.95,56.39) ; v1(20.7,57.66) 23.18,60.13 P4.24
  BOTTOM w0.127: P5.24 13.65,61.02 14.35,60.33 14.35,58.42 14.22,58.29 13.97,58.29 13.84,58.42 13.84,59.63 13.66,59.82 13.39,59.82 13.21,59.63 13.21,57.78 13.08,57.66 12.83,57.66 12.7,57.78 12.7,58.29 12.57,58.42 12.32,58.42 12.19,58.29 12.19,57.15 v1(12.95,56.39) 13.46,56.39 13.72,56.64 19.68,56.64 v1(20.7,57.66)
CLKOUT2: length 6.3
  TOP w0.127: R10.1 67.94,6.48 69.22,5.21 69.22,3.17 P2.41
DMAR: length 62.4
  TOP w0.127: v2(37.3,33.42) U4.D6 ; P2.42 70.48,6.99 56.13,21.34 34.04,21.34 32.38,22.99 32.38,29.67 v1(33.2,30.48)
  BOTTOM w0.127: v1(33.2,30.48) 33.91,31.19 33.91,31.62 35.94,33.66 35.94,34.04 36.22,34.32 36.8,34.32 37.3,33.82 v2(37.3,33.42)
GPIO0_4: length 76.1
  TOP w0.102: U4.A6 36.92,31.88 36.58,31.88
  TOP w0.127: 36.58,31.88 34.92,30.23 34.92,22.99 v1(34.29,22.35)
  BOTTOM w0.127: R44.2 10.41,51.94 22.86,39.5 22.86,29.97 30.48,22.35 v1(34.29,22.35) 41.4,15.24 41.4,8.38 40.01,6.99 P2.18
GPIO0_5: length 12
  TOP w0.127: P2.17 41.27,3.17 41.27,5.84 43.81,8.38 U3.2
GPIO0_30: length 82.8
  TOP w0.127: P4.11 16.19,60.83 16,60.64 16,59.31 16.51,58.8 16.51,57.4 17.53,56.39 17.53,53.98 v1(16.76,53.21)
  BOTTOM w0.127: P2.11 33.53,3.05 40.39,3.05 41.02,3.68 41.02,6.99 42.67,8.64 42.67,14.73 34.54,22.86 30.73,22.86 24.38,29.21 24.38,39.88 16,48.26 16,52.45 v1(16.76,53.21)
GPMC_AD0: length 74.3
  TOP w0.127: R13.1 v1(46.35,34.92)
  BOTTOM w0.127: P1.25 51.31,49.02 60.83,49.02 61.09,48.77 61.09,32.13 60.83,31.88 53.85,31.88 53.59,32.13 53.59,46.1 53.34,46.35 49.53,46.35 49.28,46.1 49.28,44.2 49.53,43.94 51.82,43.94 52.07,43.69 52.07,35.18 51.82,34.92 v1(46.35,34.92)
GPMC_AD1: length 72.6
  TOP w0.127: R16.1 v1(46.35,36.2)
  BOTTOM w0.127: P1.24 46.48,51.56 46.48,49.66 47.5,48.64 60.33,48.64 60.58,48.39 60.58,36.2 60.33,35.94 54.36,35.94 54.1,36.2 54.1,46.48 53.85,46.74 49.15,46.74 48.9,46.48 48.9,43.69 49.15,43.43 51.31,43.43 51.56,43.18 51.56,35.69 51.31,35.43 46.61,35.43 46.35,35.69 v1(46.35,36.2)
GPMC_AD2: length 53.2
  TOP w0.127: R19.1 v1(46.35,33.66) ; P1.5 27.3,47.62 39.75,47.62 42.93,44.45 v1(49.78,44.45)
  BOTTOM w0.127: v1(49.78,44.45) 49.78,44.96 50.04,45.21 51.44,45.21 52.58,44.07 52.58,33.02 52.32,32.77 47.34,32.77 47.12,32.99 47.12,33.3 47.34,33.53 48.16,33.53 48.39,33.75 48.39,34.07 48.16,34.29 46.99,34.29 v1(46.35,33.66)
GPMC_AD3: length 53
  TOP w0.127: v1(49.78,45.72) 48.83,44.77 43.37,44.77 40.2,47.94 27.62,47.94 26.04,49.53 26.04,51.44 P1.6 ; R23.1 v1(46.35,32.38)
  BOTTOM w0.127: v1(46.35,32.38) 52.83,32.38 53.09,32.64 53.09,44.32 51.69,45.72 v1(49.78,45.72)
GPMC_AD4: length 73.9
  TOP w0.127: R12.1 v1(46.35,31.11)
  BOTTOM w0.127: v1(46.35,31.11) 60.86,31.11 61.09,30.89 61.09,30.58 60.86,30.35 50.64,30.35 50.42,30.13 50.42,29.81 50.64,29.59 61.34,29.59 61.59,29.84 61.59,50.67 61.09,51.18 48.64,51.18 P1.23
GPMC_AD5: length 69.3
  TOP w0.127: R28.1 v1(46.35,29.84)
  BOTTOM w0.127: P1.22 46.23,53.85 48.51,53.85 48.9,53.47 48.9,51.94 49.28,51.56 63.75,51.56 64.14,51.18 64.14,28.07 63.88,27.81 46.61,27.81 46.35,28.07 46.35,28.57 46.61,28.83 48.39,28.83 48.64,29.08 48.64,29.59 48.39,29.84 v1(46.35,29.84)
GPMC_AD6: length 49.2
  TOP w0.127: R29.1 46.35,28.57 47.75,29.97 47.75,42.16 46.23,43.69 42.16,43.69 40.89,44.96 36.96,44.96 36.7,45.21 36.7,45.72 36.96,45.97 38.86,45.97 39.12,46.23 39.12,46.74 38.86,46.99 25.91,46.99 23.37,49.53 22.86,49.53 P1.3
GPMC_AD7: length 47.2
  TOP w0.127: R30.1 48.13,29.84 48.13,42.29 46.35,44.07 42.55,44.07 39.31,47.31 26.1,47.31 23.62,49.78 23.62,51.31 P1.4
GPMC_AD8: length 53.2
  TOP w0.127: R31.1 v1(41.91,23.37)
  BOTTOM w0.127: v1(41.91,23.37) 41.91,20.57 42.16,20.32 42.67,20.32 42.93,20.57 42.93,23.88 43.18,24.13 43.69,24.13 43.94,23.88 43.94,20.7 44.2,20.45 44.83,20.45 45.09,20.7 45.09,44.32 44.07,45.34 38.23,45.34 37.85,45.72 37.85,46.61 39.88,48.64 42.29,48.64 42.55,48.9 P1.19
GPMC_AD9: length 53.7
  TOP w0.127: v1(40.64,23.37) R32.1
  BOTTOM w0.127: v1(40.64,23.37) 40.13,22.86 39.24,22.86 37.08,25.02 32.77,25.02 26.16,31.62 26.16,45.53 26.35,45.72 26.61,45.72 26.8,45.53 26.8,41.59 26.98,41.4 27.25,41.4 27.43,41.59 27.43,47.5 28.07,48.13 33.91,48.13 34.92,49.15 P1.13
GPMC_AD10: length 52.2
  TOP w0.127: R33.1 v1(39.37,23.37)
  BOTTOM w0.127: P1.14 35.94,51.69 37.72,51.69 38.73,50.67 38.73,49.66 36.83,47.75 31.24,47.75 28.07,44.58 28.07,38.58 27.84,38.35 27.53,38.35 27.3,38.58 27.3,39.53 27.08,39.75 26.77,39.75 26.54,39.53 26.54,31.88 33.02,25.4 37.34,25.4 v1(39.37,23.37)
GPMC_AD11: length 65.5
  TOP w0.127: R34.1 v1(38.1,23.37)
  BOTTOM w0.127: v1(38.1,23.37) 38.99,22.48 40.51,22.48 41.15,23.11 41.15,25.27 44.32,28.45 44.32,43.05 42.93,44.45 31.24,44.45 29.84,43.05 29.84,38.61 29.72,38.48 29.46,38.48 29.34,38.61 29.34,44.58 32.13,47.37 37.21,47.37 P1.17
GPMC_AD12: length 51.4
  TOP w0.127: R35.1 v1(36.83,23.37)
  BOTTOM w0.127: v1(36.83,23.37) 35.94,24.26 30.61,24.26 25.27,29.59 25.27,40.51 21.59,44.2 21.59,48.39 22.23,49.02 33.02,49.02 33.46,49.47 33.46,51.63 P1.12
GPMC_AD13: length 54.7
  TOP w0.127: R36.1 v1(33.02,23.37)
  BOTTOM w0.127: P1.11 30.99,51.56 17.14,51.56 16.51,50.93 16.51,48.51 24.89,40.13 24.89,29.34 30.35,23.88 33.51,23.88 33.66,23.73 33.66,23.52 33.51,23.37 v1(33.02,23.37)
GPMC_AD14: length 53.1
  TOP w0.127: R37.1 v1(34.29,23.37)
  BOTTOM w0.127: v1(34.29,23.37) 34.8,23.37 37.08,21.08 40.13,21.08 41.4,22.35 41.4,25.02 44.7,28.32 44.7,43.31 43.18,44.83 37.08,44.83 36.83,45.09 36.83,46.35 39.5,49.02 40.51,49.02 41.27,49.78 41.27,50.67 40.51,51.44 38.73,51.44 P1.16
GPMC_AD15: length 51.5
  TOP w0.127: R38.1 v1(35.56,23.37)
  BOTTOM w0.127: v1(35.56,23.37) 36.07,22.86 37.08,22.86 37.34,23.11 37.34,24.13 36.83,24.64 32.51,24.64 25.65,31.5 25.65,40.89 24.38,42.16 24.38,47.88 25.02,48.51 33.15,48.51 33.85,49.21 33.85,50.74 34.42,51.31 36.32,51.31 P1.15
GPMC_CLK: length 67.2
  TOP w0.127: R39.1 v1(46.35,38.73)
  BOTTOM w0.127: v1(46.35,38.73) 45.97,38.73 45.85,38.61 45.85,23.75 46.1,23.5 46.86,23.5 47.12,23.75 47.12,26.92 47.37,27.18 48.13,27.18 48.39,26.92 48.39,20.57 48.13,20.32 45.97,20.32 45.47,20.83 45.47,47.5 43.81,49.15 43.81,50.93 43.31,51.44 41.27,51.44 P1.18
GPMC_NADV_ALE: length 54
  TOP w0.127: P1.7 29.21,48.26 40.64,48.26 43.81,45.09 47.69,45.09 v1(48.32,45.72) ; R40.1 v1(46.35,37.47)
  BOTTOM w0.127: v1(46.35,37.47) 46.99,37.47 47.24,37.21 47.24,36.07 47.5,35.81 50.93,35.81 51.18,36.07 51.18,42.67 50.93,42.93 49.91,42.93 49.66,42.67 49.66,37.34 49.4,37.08 48.58,37.08 48.32,37.34 v1(48.32,45.72)
GPMC_NCS1: length 79.5
  TOP w0.127: v1(46.35,42.55) 46.35,42.93 46.1,43.18 44.83,43.18 44.58,42.93 R43.2 44.58,42.04 44.45,41.91 43.43,41.91 42.29,40.77 42.29,37.97 40.89,36.58 39.62,36.58 U4.J2
  BOTTOM w0.127: P1.21 46.99,48.26 59.82,48.26 60.07,48.01 60.07,36.7 59.82,36.45 59.44,36.45 59.18,36.7 59.18,41.02 58.93,41.27 58.55,41.27 58.29,41.02 58.29,36.7 58.04,36.45 57.66,36.45 57.4,36.7 57.4,47.75 57.28,47.88 46.1,47.88 45.85,47.62 45.85,45.34 46.35,44.83 v1(46.35,42.55)
GPMC_NOE_NRE: length 60.2
  TOP w0.127: U4.H2 39.78,36.24 41.06,36.24 42.55,37.72 42.55,40.39 43.43,41.27 R41.2 44.58,40.77 44.7,40.64 46.67,40.64 v1(47.31,41.27) ; v1(46.35,45.72) 44.2,45.72 43.69,46.23 43.69,47.5 43.94,47.75 52.97,47.75 53.21,47.99 53.21,48.34 52.97,48.58 29.78,48.58 28.57,49.78 28.57,51.44 P1.8
  BOTTOM w0.127: v1(47.31,41.27) 47.31,44.77 v1(46.35,45.72)
GPMC_NWE: length 61.6
  TOP w0.127: v1(47.31,40.01) 46.67,39.37 44.7,39.37 44.58,39.5 R42.2 43.43,40.01 42.8,39.37 42.8,37.47 41.26,35.92 U4.H1 ; P1.10 31.11,51.44 31.11,49.28 31.5,48.9 53.47,48.9 53.85,48.51 53.85,46.1 53.47,45.72 51.56,45.72 51.31,45.97 51.31,46.99 51.05,47.24 44.45,47.24 44.2,46.99 44.2,46.61 44.45,46.35 46.67,46.35 v1(47.31,45.72)
  BOTTOM w0.127: v1(47.31,45.72) 47.94,45.09 47.94,40.64 v1(47.31,40.01)
GPMCCLK: length 6.6
  TOP w0.127: U4.G1 41.27,35.43 43.05,37.21 43.05,38.23 43.56,38.73 R39.2
I2C2_SCL: length 110.8
  TOP w0.127: v1(13.97,57.66) 13.72,57.4 11.05,57.4 10.92,57.53 10.92,59.44 12.38,60.9 P4.5 12.38,63.18 11.94,63.63 8.89,63.63 7.87,62.61 7.87,53.09 22.86,38.1 22.86,29.46 34.16,18.16 42.8,18.16 45.78,15.18 45.78,7.68 43.81,5.71 43.81,3.17 P2.19
  BOTTOM w0.127: P5.5 24.45,60.9 23.5,59.94 22.35,59.94 19.3,56.9 14.73,56.9 v1(13.97,57.66)
I2C2_SDA: length 100.1
  TOP w0.127: P2.20 42.55,5.4 45.21,8.06 45.21,14.99 42.42,17.78 33.78,17.78 22.23,29.34 22.23,38.1 7.49,52.83 7.49,62.74 8.76,64.01 12.83,64.01 13.65,63.18 ; P4.7 v1(13.65,63.12) 13.65,63.18 ; 13.65,63.18 14.61,64.14 22.16,64.14 v1(23.18,63.12)
  BOTTOM w0.127: P5.7 v1(23.18,63.12)
LDO_EN: length 19
  TOP w0.127: U1.5 40.35,15.55 40.02,15.88 R3.1 ; U2.5 30.82,15.58 32.64,17.4 39.77,17.4 40.02,17.14 R3.1 ; R3.1 42.93,16.51 44.47,14.97 U3.4
NADV: length 7.4
  TOP w0.127: R40.2 v1(43.56,37.47) ; U4.G3 v2(38.97,36.43)
  BOTTOM w0.127: v2(38.97,36.43) 39.45,35.94 42.04,35.94 v1(43.56,37.47)
SW1_A0: length 134.7
  TOP w0.127: v1(34.54,18.8) 35.43,19.68 v1(44.7,19.68) ; v1(27.62,63.12) P4.29 ; SW1.4 v1(75.56,41.91) ; v1(10.79,66.17) v1(10.79,64.52)
  BOTTOM w0.127: v1(27.62,63.12) 27.62,63.56 26.8,64.39 14.99,64.39 13.21,66.17 v1(10.79,66.17) ; v1(34.54,18.8) 32.77,18.8 22.1,29.46 22.1,39.12 8.76,52.45 8.76,58.99 9.21,59.44 P5.29 9.21,63.31 10.41,64.52 v1(10.79,64.52) ; v1(44.7,19.68) 57.28,19.68 67.31,29.72 67.31,33.66 v1(75.56,41.91)
SW1_A1: length 132.2
  TOP w0.127: P4.30 26.99,63.56 26.16,64.39 11.81,64.39 v1(11.81,64.52) ; SW1.3 v1(78.11,41.91) ; v1(44.7,18.8) v1(35.43,18.8)
  BOTTOM w0.127: v1(78.11,41.91) 68.96,32.77 68.96,30.48 57.28,18.8 v1(44.7,18.8) ; v1(35.43,18.8) 34.8,19.43 32.77,19.43 22.48,29.72 22.48,39.24 9.4,52.32 9.4,59.05 9.84,59.5 P5.30 9.84,63.44 10.29,63.88 11.18,63.88 v1(11.81,64.52)
SYS_5V: length 129
  TOP w0.381: R2.2 v1(36.83,11.43) ; v1(17.78,63.12) 17.46,62.8 P4.13 ; R56.2 R55.2 8.13,7.75 9.53,6.35 25.4,6.35 P2.8 ; v1(19.05,63.12) 18.73,62.8 P4.15 ; R7.2 v1(27.3,11.43)
  BOTTOM w0.381: P5.15 18.1,62.8 v1(17.78,63.12) v1(19.05,63.12) 19.37,62.8 P5.13
  BOTTOM w0.635: v1(27.3,11.43) 21.34,17.4 21.34,38.99 7.24,53.09 7.24,62.36 10.29,65.41 12.95,65.41 14.48,63.88 17.4,63.88 17.78,63.5 18.67,63.5 v1(19.05,63.12)
  BOTTOM w0.762: P2.8 v1(27.3,11.43) 28.07,11.43 28.96,10.54 35.94,10.54 v1(36.83,11.43)
  BOTTOM w1.27: P2.8 P2.7
N17041351: length 5.6
  TOP w0.127: R3.2 38.72,15.88 38.39,15.55 U1.8 37.54,14.81 36.83,14.1 34.92,14.1
N17041584: length 3.8
  TOP w0.127: U2.8 28.02,14.81 27.3,14.1 25.4,14.1
N17068057: length 8.8
  TOP w0.127: R59.2 30.35,40.64 30.86,40.13 31.75,40.13 33.27,38.61 34.78,38.61 U4.L9
N17096906: length 2.6
  TOP w0.127: Q1.6 1.76,13.45 1.52,13.21 1.52,12.57 1.91,12.19 D2.1
N17096909: length 1.3
  TOP w0.127: D2.2 R56.1
N17096919: length 4.2
  TOP w0.127: D1.1 2.92,12.43 2.92,14.48 3.19,14.75 Q1.3
N17096922: length 1.3
  TOP w0.127: D1.2 R55.1

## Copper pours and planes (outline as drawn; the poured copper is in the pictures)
DGND on TOP (solid shape): 31.5,12.57 28.19,12.57 28.19,14.1 31.5,14.1
DGND on TOP (solid shape): 41.02,12.57 37.72,12.57 37.72,14.1 41.02,14.1
DGND on BOTTOM (solid shape): 31.5,12.06 28.19,12.06 28.19,14.61 31.5,14.61
DGND on BOTTOM (solid shape): 41.02,12.06 37.72,12.06 37.72,14.61 41.02,14.61
DGND on LYR2-GND: 6.35,0.64 2.31,2.31 0.64,6.35 0.64,20.32 20.95,20.32 20.95,39.37 6.35,39.37 6.35,66.67 14.73,66.67 14.73,64.39 22.1,64.39 22.1,66.67 30.48,66.67 30.48,53.98 73.66,53.98 82.19,50.44 85.72,41.91 85.72,12.7 82.19,4.17 73.66,0.64
VDD_1V8 on TOP: 27.69,45.97 28.45,45.21 33.91,45.21 36.07,43.05 38.86,43.05 40.64,41.27 40.64,40.64 40.89,40.39 41.15,40.39 41.4,40.13 41.4,39.88 41.15,39.62 40.89,39.62 39.88,38.61 39.88,37.47 40.01,37.34 40.39,37.34 40.64,37.59 40.64,38.23 40.89,38.48 41.78,38.48 42.04,38.73 42.04,42.55 40.13,44.45 36.83,44.45 34.54,46.74 27.81,46.74 27.69,46.61
VDD_1V8 on LYR3-PWR: 40.39,41.15 41.15,41.15 41.4,40.89 41.4,38.86 41.15,38.61 40.89,38.61 40.51,38.23 40.51,36.07 38.1,33.66 38.1,33.15 38.48,32.77 41.15,32.77 41.4,32.51 41.4,8.89 41.15,8.64 36.32,8.64 36.07,8.89 36.07,11.81 35.69,12.19 32.26,12.19 32,12.45 32,20.57 31.11,21.46 31.11,30.73 34.29,33.91 35.56,33.91 35.81,34.16 35.81,34.8 33.53,37.08 33.53,37.47 33.78,37.72 34.16,37.72 35.81,36.07 39.24,36.07 40.13,36.96 40.13,40.89
VDD_1V8 on LYR3-PWR: 12.19,62.99 12.19,63.75 12.57,64.14 24.13,64.14 24.51,63.75 24.51,49.53 26.92,47.12 26.92,46.23 27.18,45.97 30.23,45.97 30.48,46.23 30.48,66.67 22.1,66.67 22.1,64.52 14.73,64.52 14.73,66.67 6.35,66.67 6.35,62.74 11.94,62.74
VDD_2V8 on TOP: 34.04,39.12 34.29,39.37 34.29,41.4 35.56,42.67 35.56,43.18 33.78,44.96 28.32,44.96 26.54,46.74 24.89,46.74 24.77,46.61 24.77,46.23 27.43,43.56 31.75,43.56 32.26,43.05 32.26,40.13 33.27,39.12
VDD_2V8 on LYR3-PWR: 15.11,63.5 21.72,63.5 22.1,63.12 22.1,55.5 20.83,54.23 20.83,48.77 23.62,45.97 26.42,45.97 26.67,46.23 26.67,46.99 24.26,49.4 24.26,63.63 24,63.88 12.7,63.88 12.45,63.63 12.45,62.99 12.7,62.74 14.35,62.74
VDD_2V8 on LYR3-PWR: 37.08,43.43 36.83,43.69 33.02,43.69 32.77,43.43 32.77,41.15 26.67,35.05 26.67,8.89 26.92,8.64 31.5,8.64 31.75,8.89 31.75,20.45 30.86,21.34 30.86,30.86 34.16,34.16 35.43,34.16 35.56,34.29 35.56,34.67 33.27,36.96 33.27,37.59 33.66,37.97 34.29,37.97 35.94,36.32 36.83,36.32 37.08,36.58
VDD_3V3 on LYR3-PWR: 6.35,0.64 2.31,2.31 0.64,6.35 0.64,20.32 20.95,20.32 20.95,39.37 6.35,39.37 6.35,62.48 14.48,62.48 15.24,63.25 21.59,63.25 21.84,62.99 21.84,55.63 20.57,54.36 20.57,48.64 23.5,45.72 30.35,45.72 30.73,46.1 30.73,53.98 73.66,53.98 82.19,50.44 85.72,41.91 85.72,12.7 82.19,4.17 73.66,0.64 ; 1 cut-out

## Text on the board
BOTTOM: BB-BONE-CAME-PCB-02 | LAYER 4 | SOLDER
Board Geometry/Soldermask Bottom: SMS
Ref Des/Silkscreen Bottom: BSLK
User.Comments: Camera Cape
TOP: LAYER 1 | COMPONENT
Board Geometry/Soldermask Top: SMC
Ref Des/Silkscreen Top: REV____ | BeagleBone Camera Expansion Cape | TSLK
LYR2-GND: LAYER 2 | GROUND
LYR3-PWR: LAYER 3 | POWER
DISPLAY_TOP: SPC
DIMENSION: R.250 | 2 PLS.
USER_PART_NUM_TOP: TSLKC
USER_PART_NUM_BOTTOM: BSLKC
DISPLAY_BOTTOM: SPS
DEVICE_TYPE_BOTTOM: DATE | DESIGN ENGR | PROJECT ENGR | ENGR MGR | NEXT ASSEMBLY | APPROVED | CHECKED | DRAFTING | ENGR | NONE | 1 OF 1 | 10.  LAYER 1 AND 4 SHALL BE IMPEDENCE CONTROLLED, FOR 5 MIL LINES TO BE,50 OHMS. | 1   TOTAL BOARD THICKNESS SHALL BE .062 +/- 10% INCHES. | 5.  APPLY LPI SILKSCREEN OR EQUIVALENT PER THE ARTWORK COLOR:BLACK. | 4.  SOLDERMASK ON BOTH SIDES OF THE BOARD SHALL BE S.M.O.B.C., LPI, COLOR WHITE. | 3.  MINIMUM TRACE AND SPACE SHALL BE .005 OF AN INCH. | 2.  COPPER PLATED SURFACE CONDUCTORS SHALL BE THE EQUIVALENT OF 1 OZ. COPPER | 8.  FINISHED BOARD SHALL BE FREE OF BURRS ON EDGES. | 7.  DRC'S MUST BE RAN ON THE GERBERS BEFORE BUILDING BOARDS UNLESS PRIOR | 6.  PLATED THRU HOLE SIZE TOLERANCES SHALL BE +/- .003 INCH. | 9.  SURFACE FINISH SHALL BE IMMERSION SILVER. | AFTER PLATING.  PLANE LAYERS SHALL BE 1 OZ. COPPER.  AVERAGE COPPER ON | THE WALL OF THE PLATED HOLE SHALL BE PER IPC CLASS 2. | ALL MATERIAL SHALL BE NEMA GRADE FR-4 OR EQUIVALENT. (Tg>=170 DEG. C) | APPROVAL IS GIVEN IN WRITING. | UNPLATED THRU HOLE SIZE TOLERANCES SHALL BE +/- .002 INCH. | LAYER 1 | LAYER 2 | NOTES: UNLESS OTHERWISE SPECIFIED
User.9: DATE | DESIGN ENGR | PROJECT ENGR | ENGR MGR | NEXT ASSEMBLY | APPROVED | CHECKED | DRAFTING | ENGR | 1 OF 1 | TOP SIDE | BOTTOM SIDE
User.10: NONE
User.12: 1. All board outlines shall be .020 in width. | 2. All other lines shall be .012 in width. | 3. Note and misc. text shall be text block 10. | 4. View and description text shall be text block 16. | 5. Make sure that there is not any double dimensioning, | 6. Check all notes to make sure that they apply and are correct. | 7. Make sure that layer stack-up is correct. | label (REF) dim when needed.
User.16: FIGURE | SIZE | 8.0 | 12.0 | 38.0 | 40.0 | 125.0 | 43.31 | 124.02 | ALL UNITS ARE IN MILS | DRILL CHART: TOP to BOTTOM | TOLERANCE | +3.0/-3.0 | +0.0/-0.0 | PLATED | NON-PLATED | QTY | 172 | 10 | 1 | 101 | 3 | 2
